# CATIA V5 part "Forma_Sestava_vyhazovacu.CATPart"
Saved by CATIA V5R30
Part number: Forma_Sestava_vyhazovacu
Publications: "DrillHole_LeaderPin_E1010_1.1_", "DrillHole_LeaderPin_E1010_1.1__@1", "DrillHole_LeaderPin_E1010_1.2_", "DrillHole_LeaderPin_E1010_1.2__@1", "DrillHole_LeaderPin_E1010_1.3_", "DrillHole_LeaderPin_E1010_1.3__@1", "DrillHole_LeaderPin_E1010_1.4_", "DrillHole_LeaderPin_E1010_1.4__@1"
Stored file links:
  E:\Bakalarka\Model\Forma_v7\Forma_Sestava_vyhazovacu.CATPart
  E:\Bakalarka\Model\Forma_v7\Forma.CATProduct
  E:\Bakalarka\Model\Forma_v7\TlgItf_Sestava_vyhazovacu.CATProduct
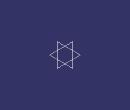
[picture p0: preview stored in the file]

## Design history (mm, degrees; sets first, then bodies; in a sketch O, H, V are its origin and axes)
Body1 (main body)
Body2 "DrillHole"
  Solid1: linked copy from another document
Body3 "DrillHole"
  Solid2: linked copy from another document
Body4 "DrillHole"
  Solid3: linked copy from another document
Body5 "DrillHole"
  Solid4: linked copy from another document
Body6 "DrillHole"
  Solid5: linked copy from another document
Body7 "DrillHole"
  Solid6: linked copy from another document
Body8 "DrillHole"
  Solid7: linked copy from another document
Body9 "DrillHole"
  Solid8: linked copy from another document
